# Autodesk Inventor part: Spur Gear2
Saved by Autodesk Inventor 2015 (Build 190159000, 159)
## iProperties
Created: 2014-06
Part Number: Spur Gear2
Material: Steel
Document SubType Name: Modeling
Designer: User
Categories: <?xml version="1.0" encoding="UTF-16"?> <MemberInstance><Categories><FamilyTemplate><FamilyTemplateParameter ValueType="xs:double" Id="1" ObjectReferenceKey="da
Density: 1 g/cm^3
Appearance: Steel
CustomPartVersion: 1
Author: User
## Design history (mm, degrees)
sketch "Sketch1"
  geometry: C1 r 10.2 at (0, 0)
  constraints: 1 centre point
  dimensions: "d0" = 20.4 diameter of C1 (= da_da)
extrude "Extrusion1" new body sketch "Sketch1" distance "d1" = 4 (= da_b); taper "d2" = 0 deg
workplane "Work Plane2"
sketch "Sketch2"
  geometry: C1 r 10.2 at (0, 0) reference; C2 r 9.4 at (0, 0)
  constraints: 1 centre point, 1 coincident
  dimensions: "d3" = 18.8 diameter of C2 (= da_dw)
feature "Pitch Diameter" sketch "Sketch2" dims "d4" = 10, "d5" = 0
workplane "Work Plane8"
workplane "Work Plane9"
feature "Spur Gear" dims "da_b" = 4, "da_d" = 18.79786, "da_aw" = 18.8, "da_da" = 20.4, "da_df" = 16.8, "da_dw" = 18.8, angle "da_beta" = 40 deg, "da_lefttooth" = 0, "da_righttooth" = 10
body "Solid1"
body "Srf1"
other parameters: "d16" = 18.8 (= da_aw), "d17" = 0, "d34" = 10 deg (computed from da_z), "d39" = 0, "d41" = 0, "d43" = 18.8 (= da_aw), "d46" = 18.8 (= da_aw), "d47" = 0, "d48" = 0
